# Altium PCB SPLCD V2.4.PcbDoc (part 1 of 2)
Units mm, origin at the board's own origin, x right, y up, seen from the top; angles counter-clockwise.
Board outline 130.07 x 120.05 mm, 4 copper layers (TopLayer, GND, PWR, BottomLayer); 151 components, 101 nets, 494 pads, 228 vias.
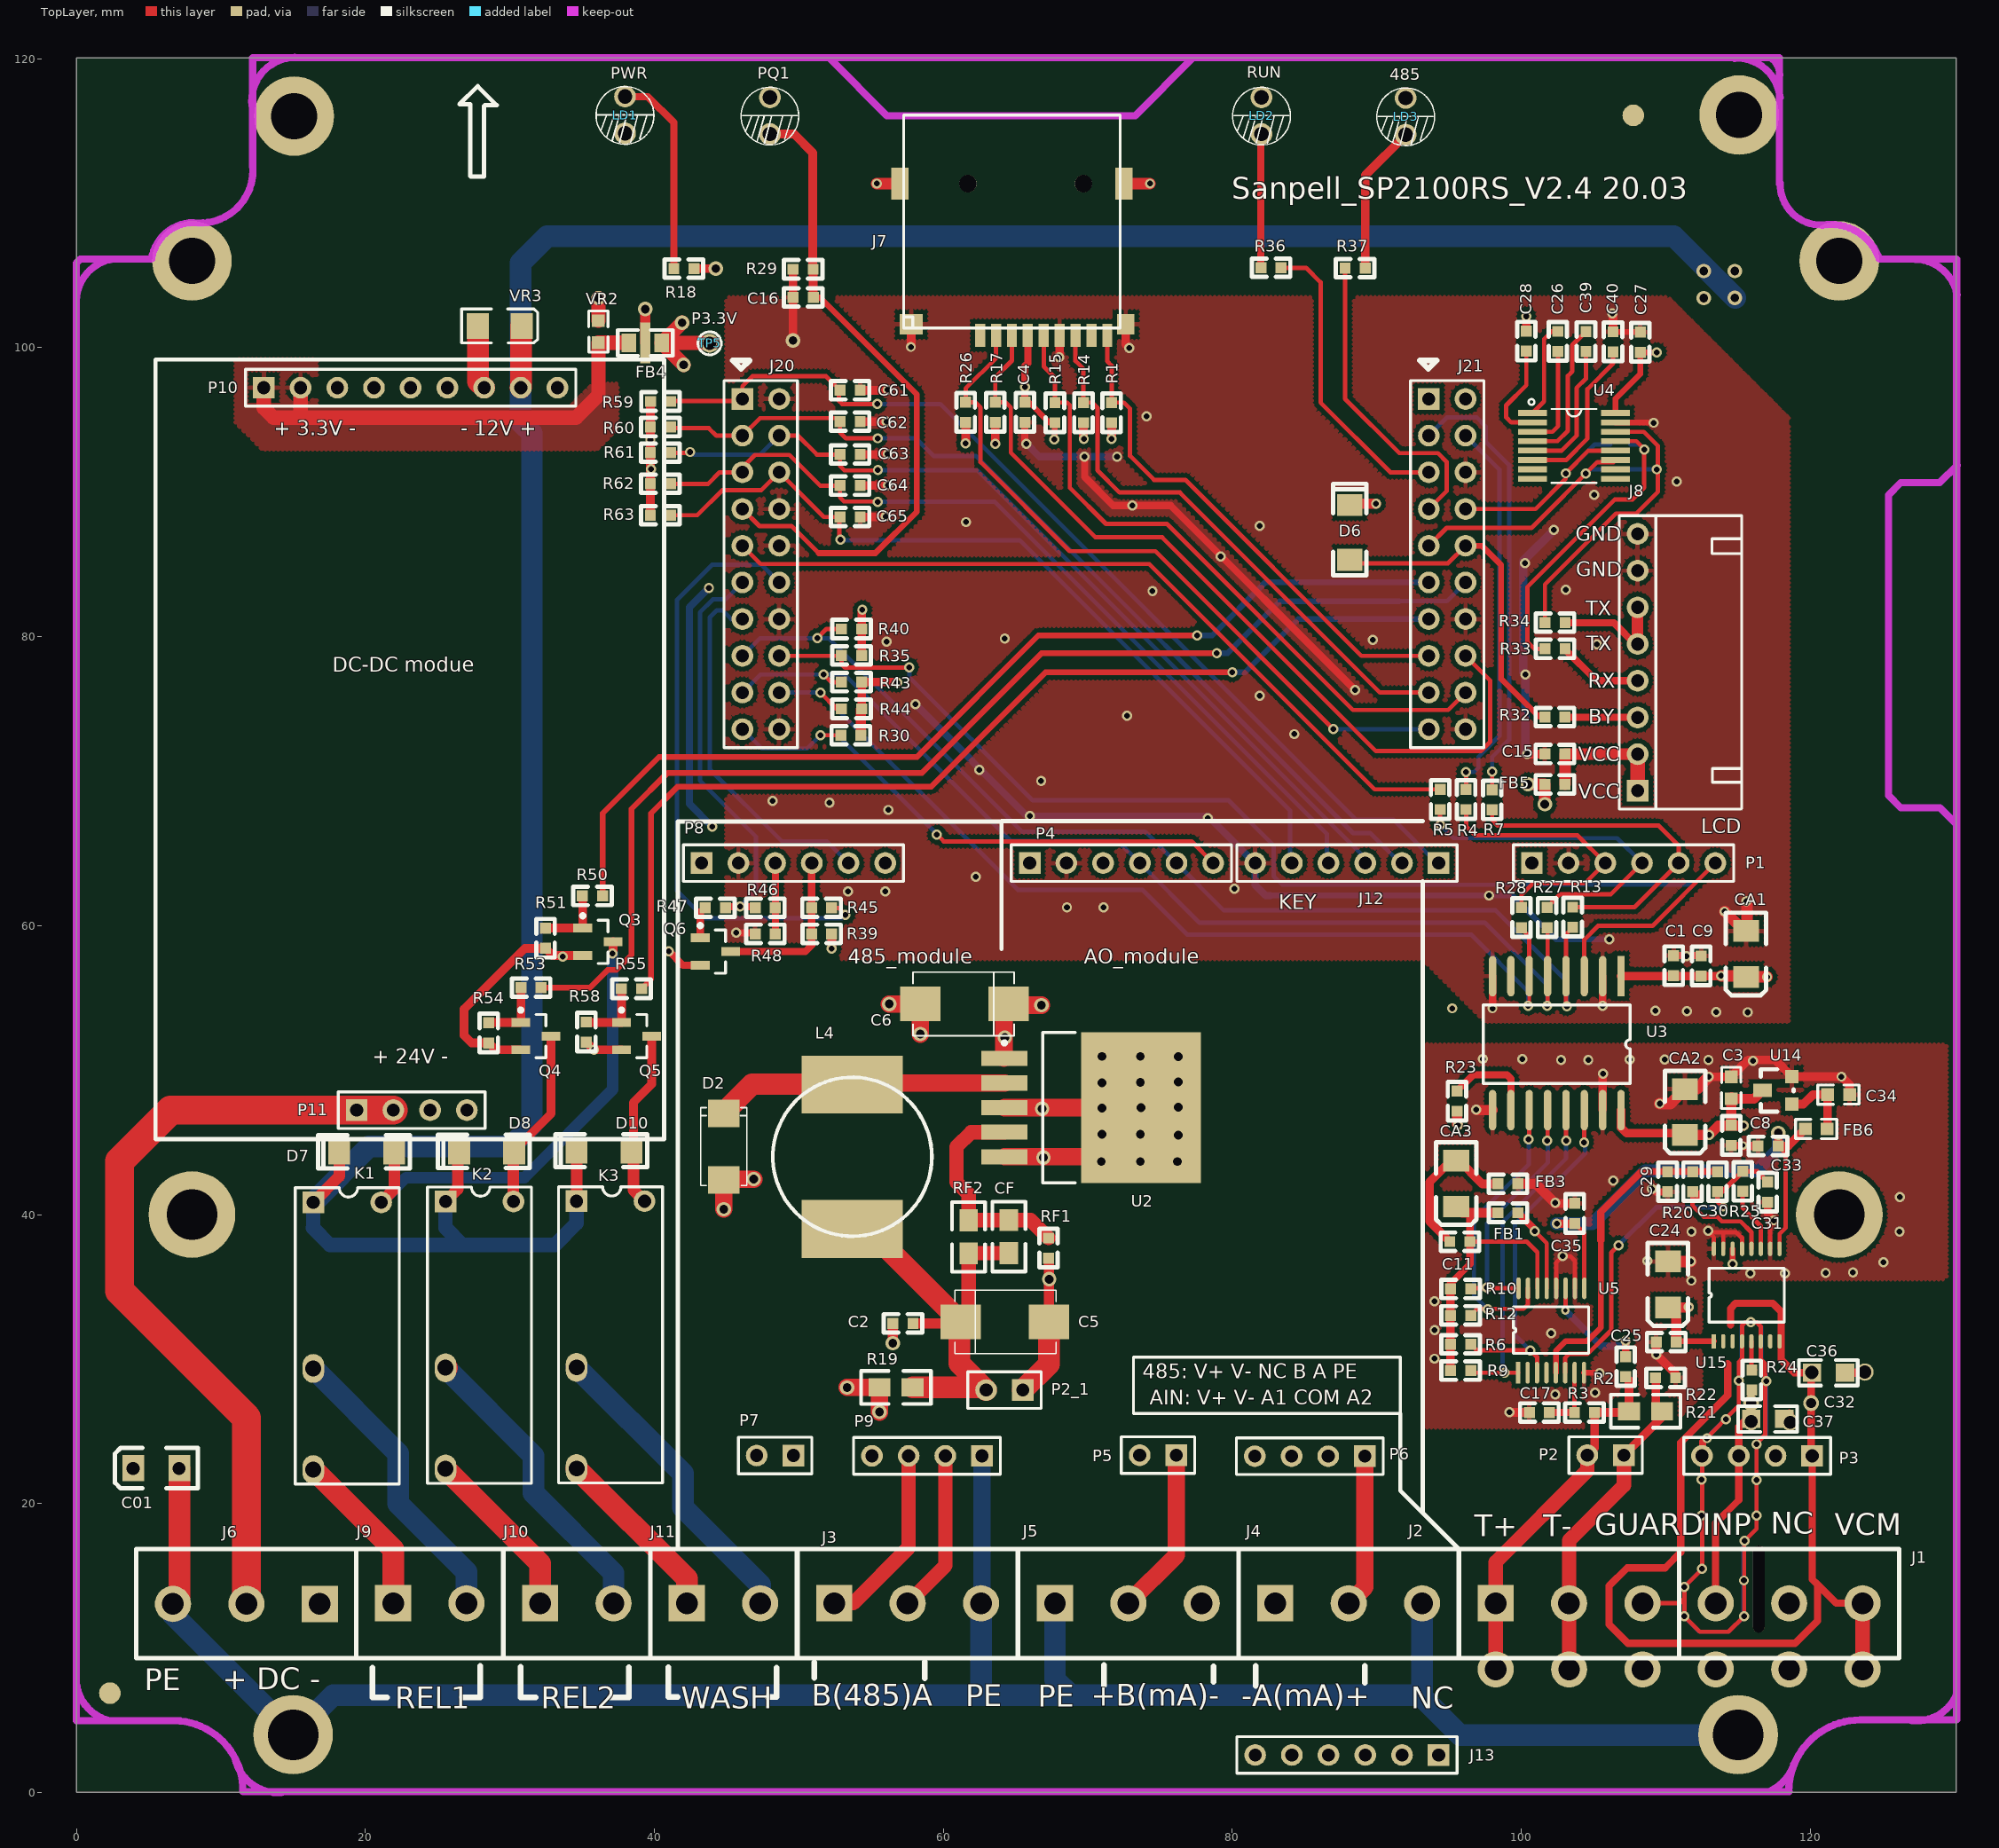
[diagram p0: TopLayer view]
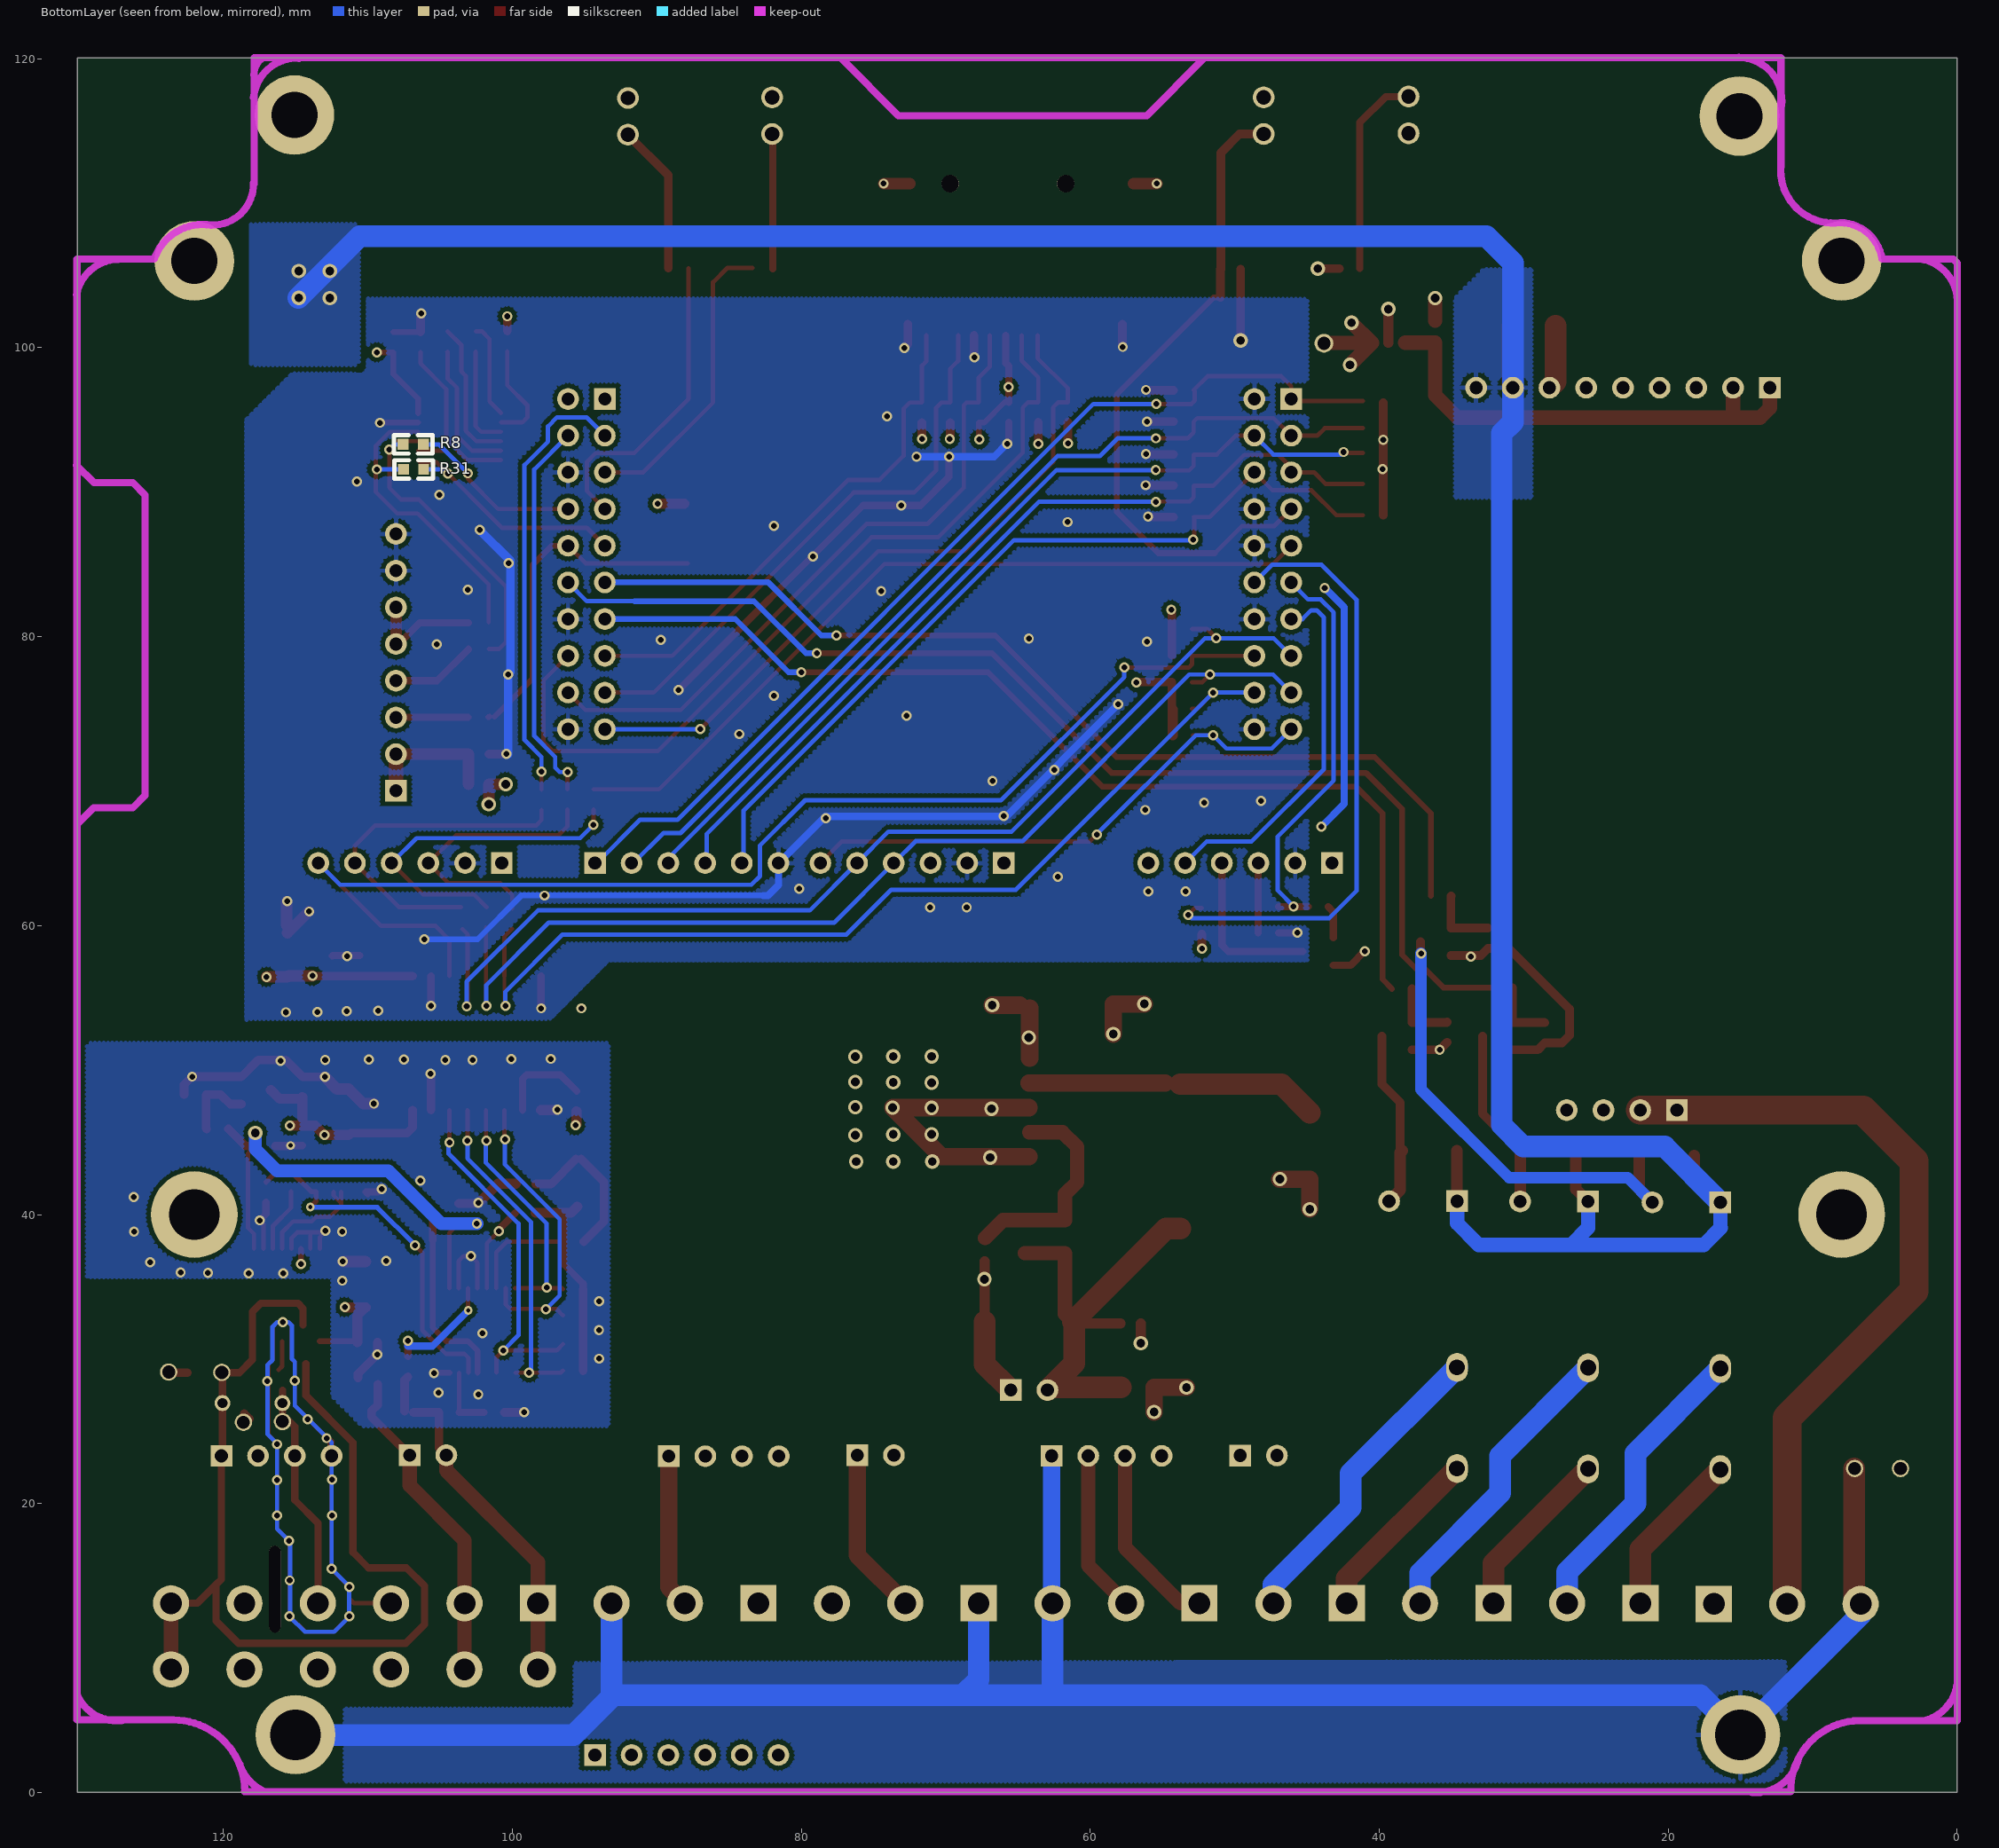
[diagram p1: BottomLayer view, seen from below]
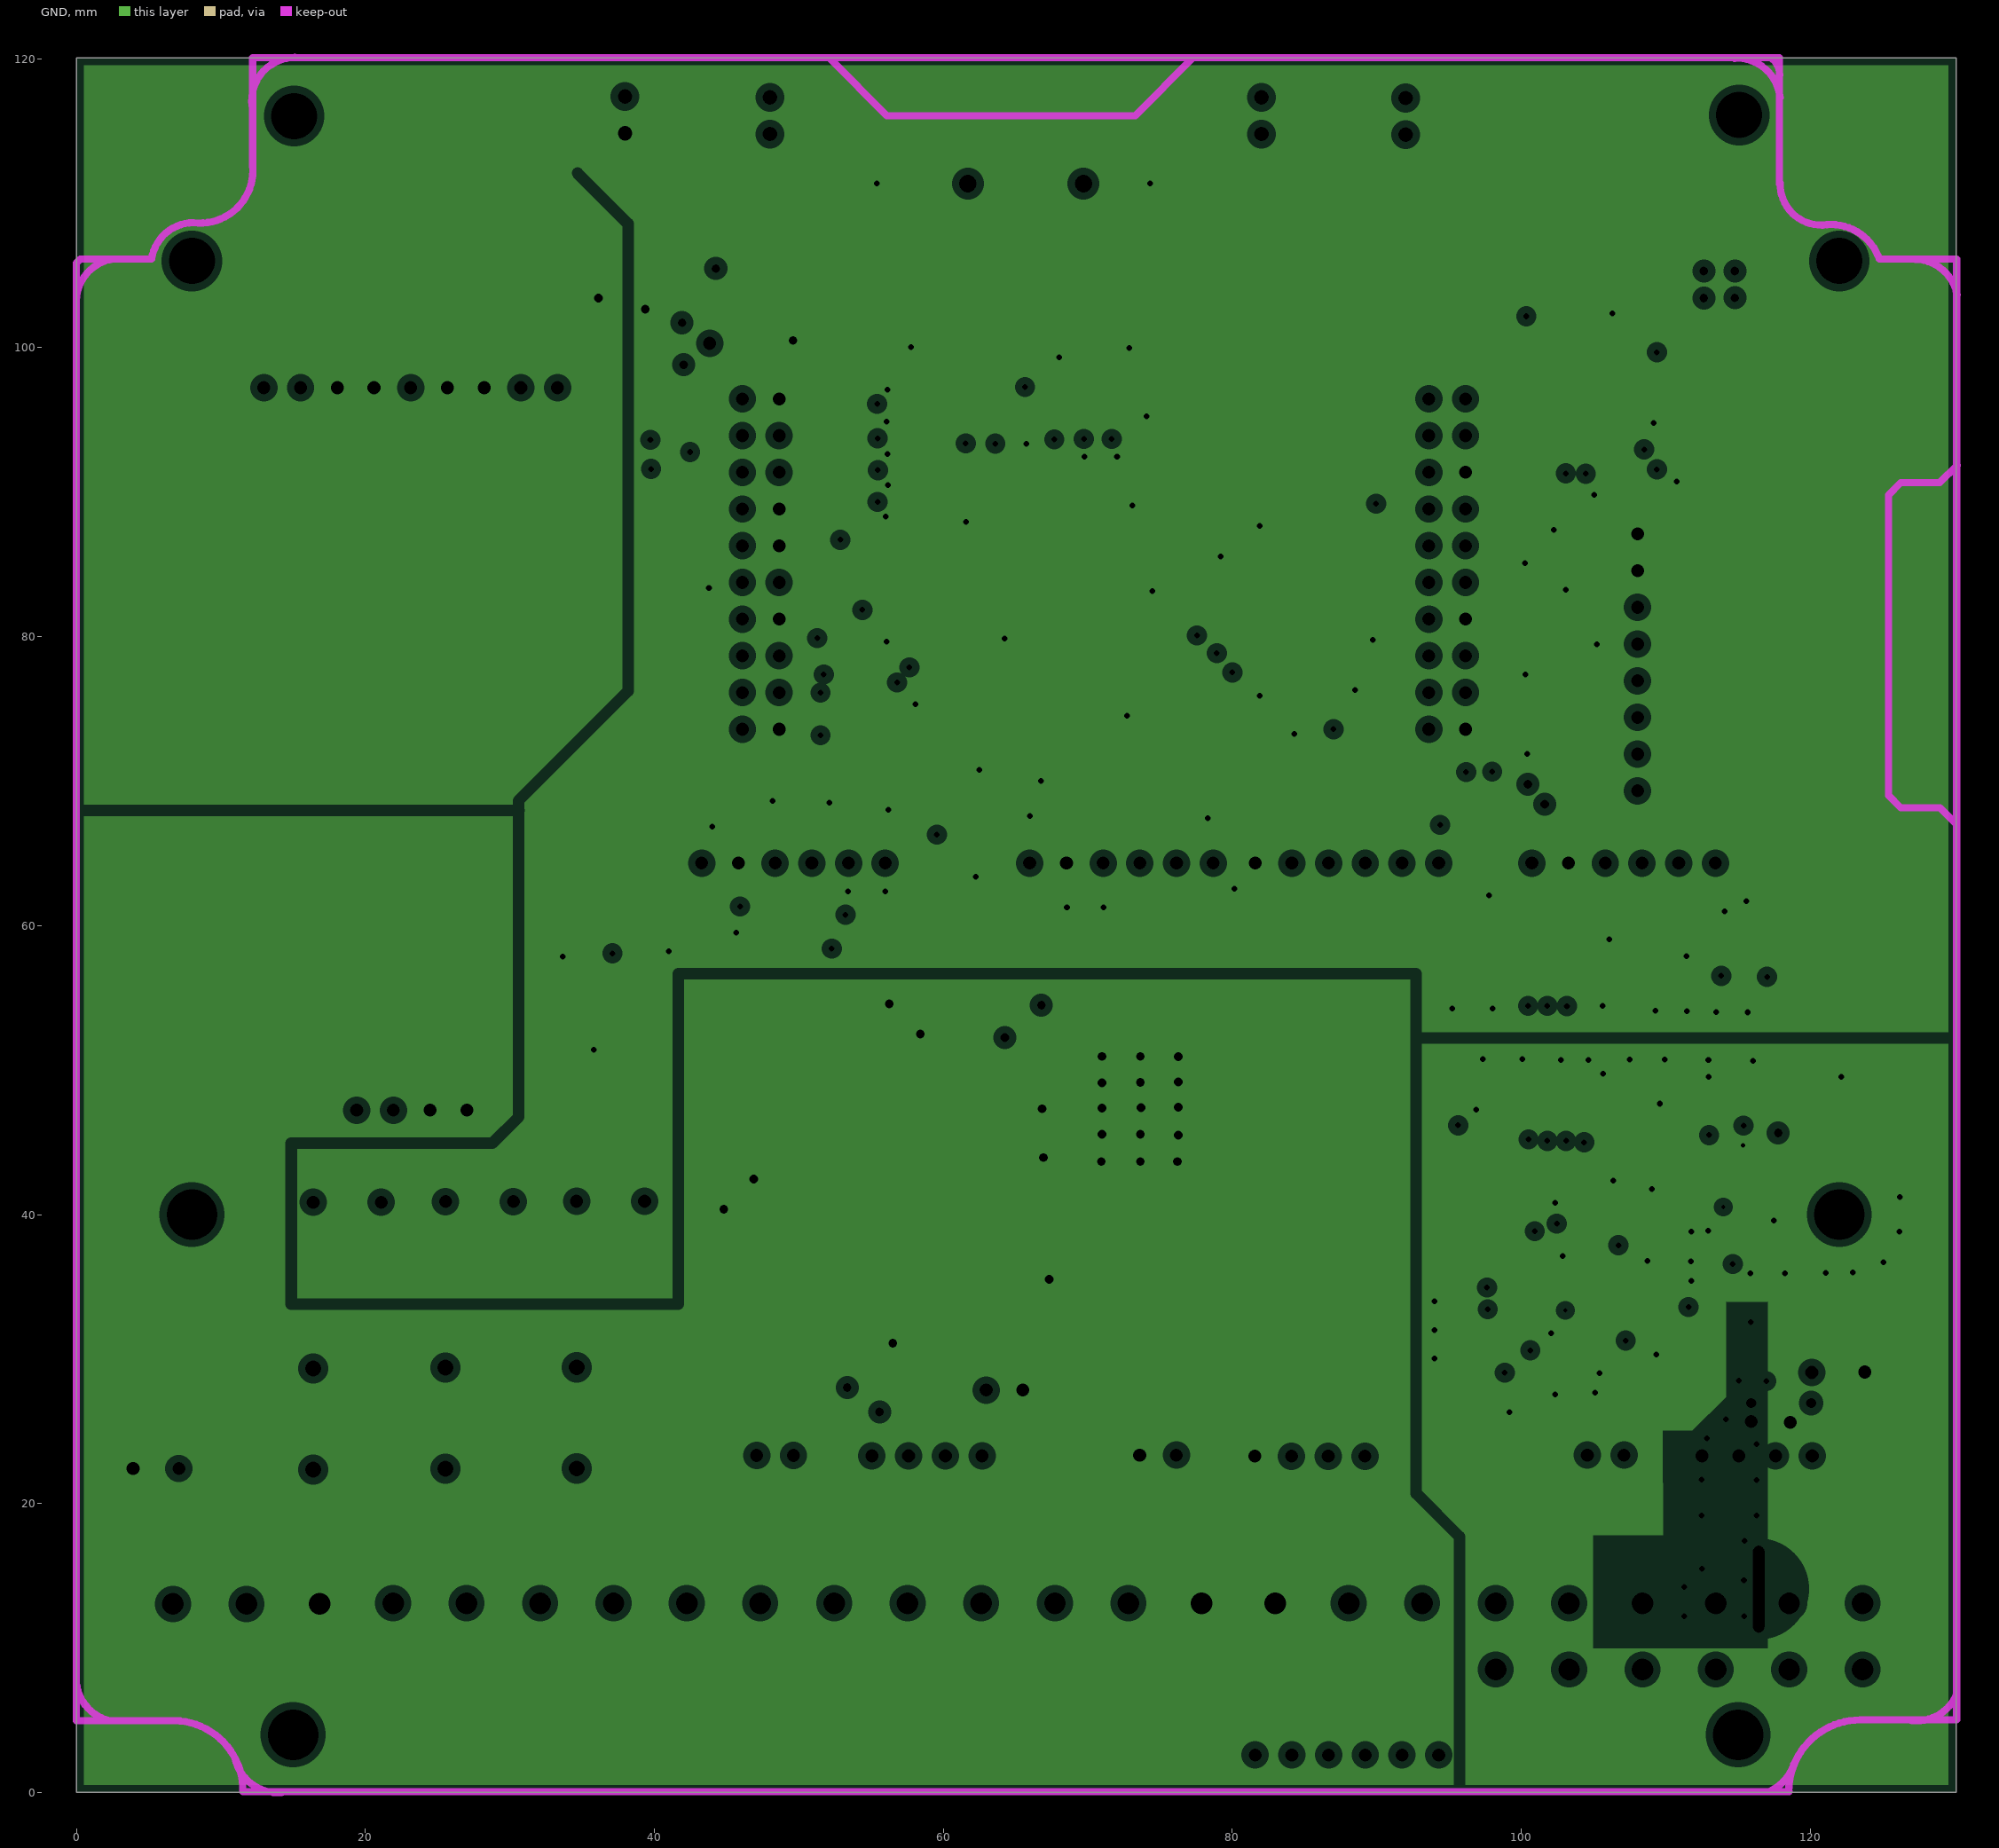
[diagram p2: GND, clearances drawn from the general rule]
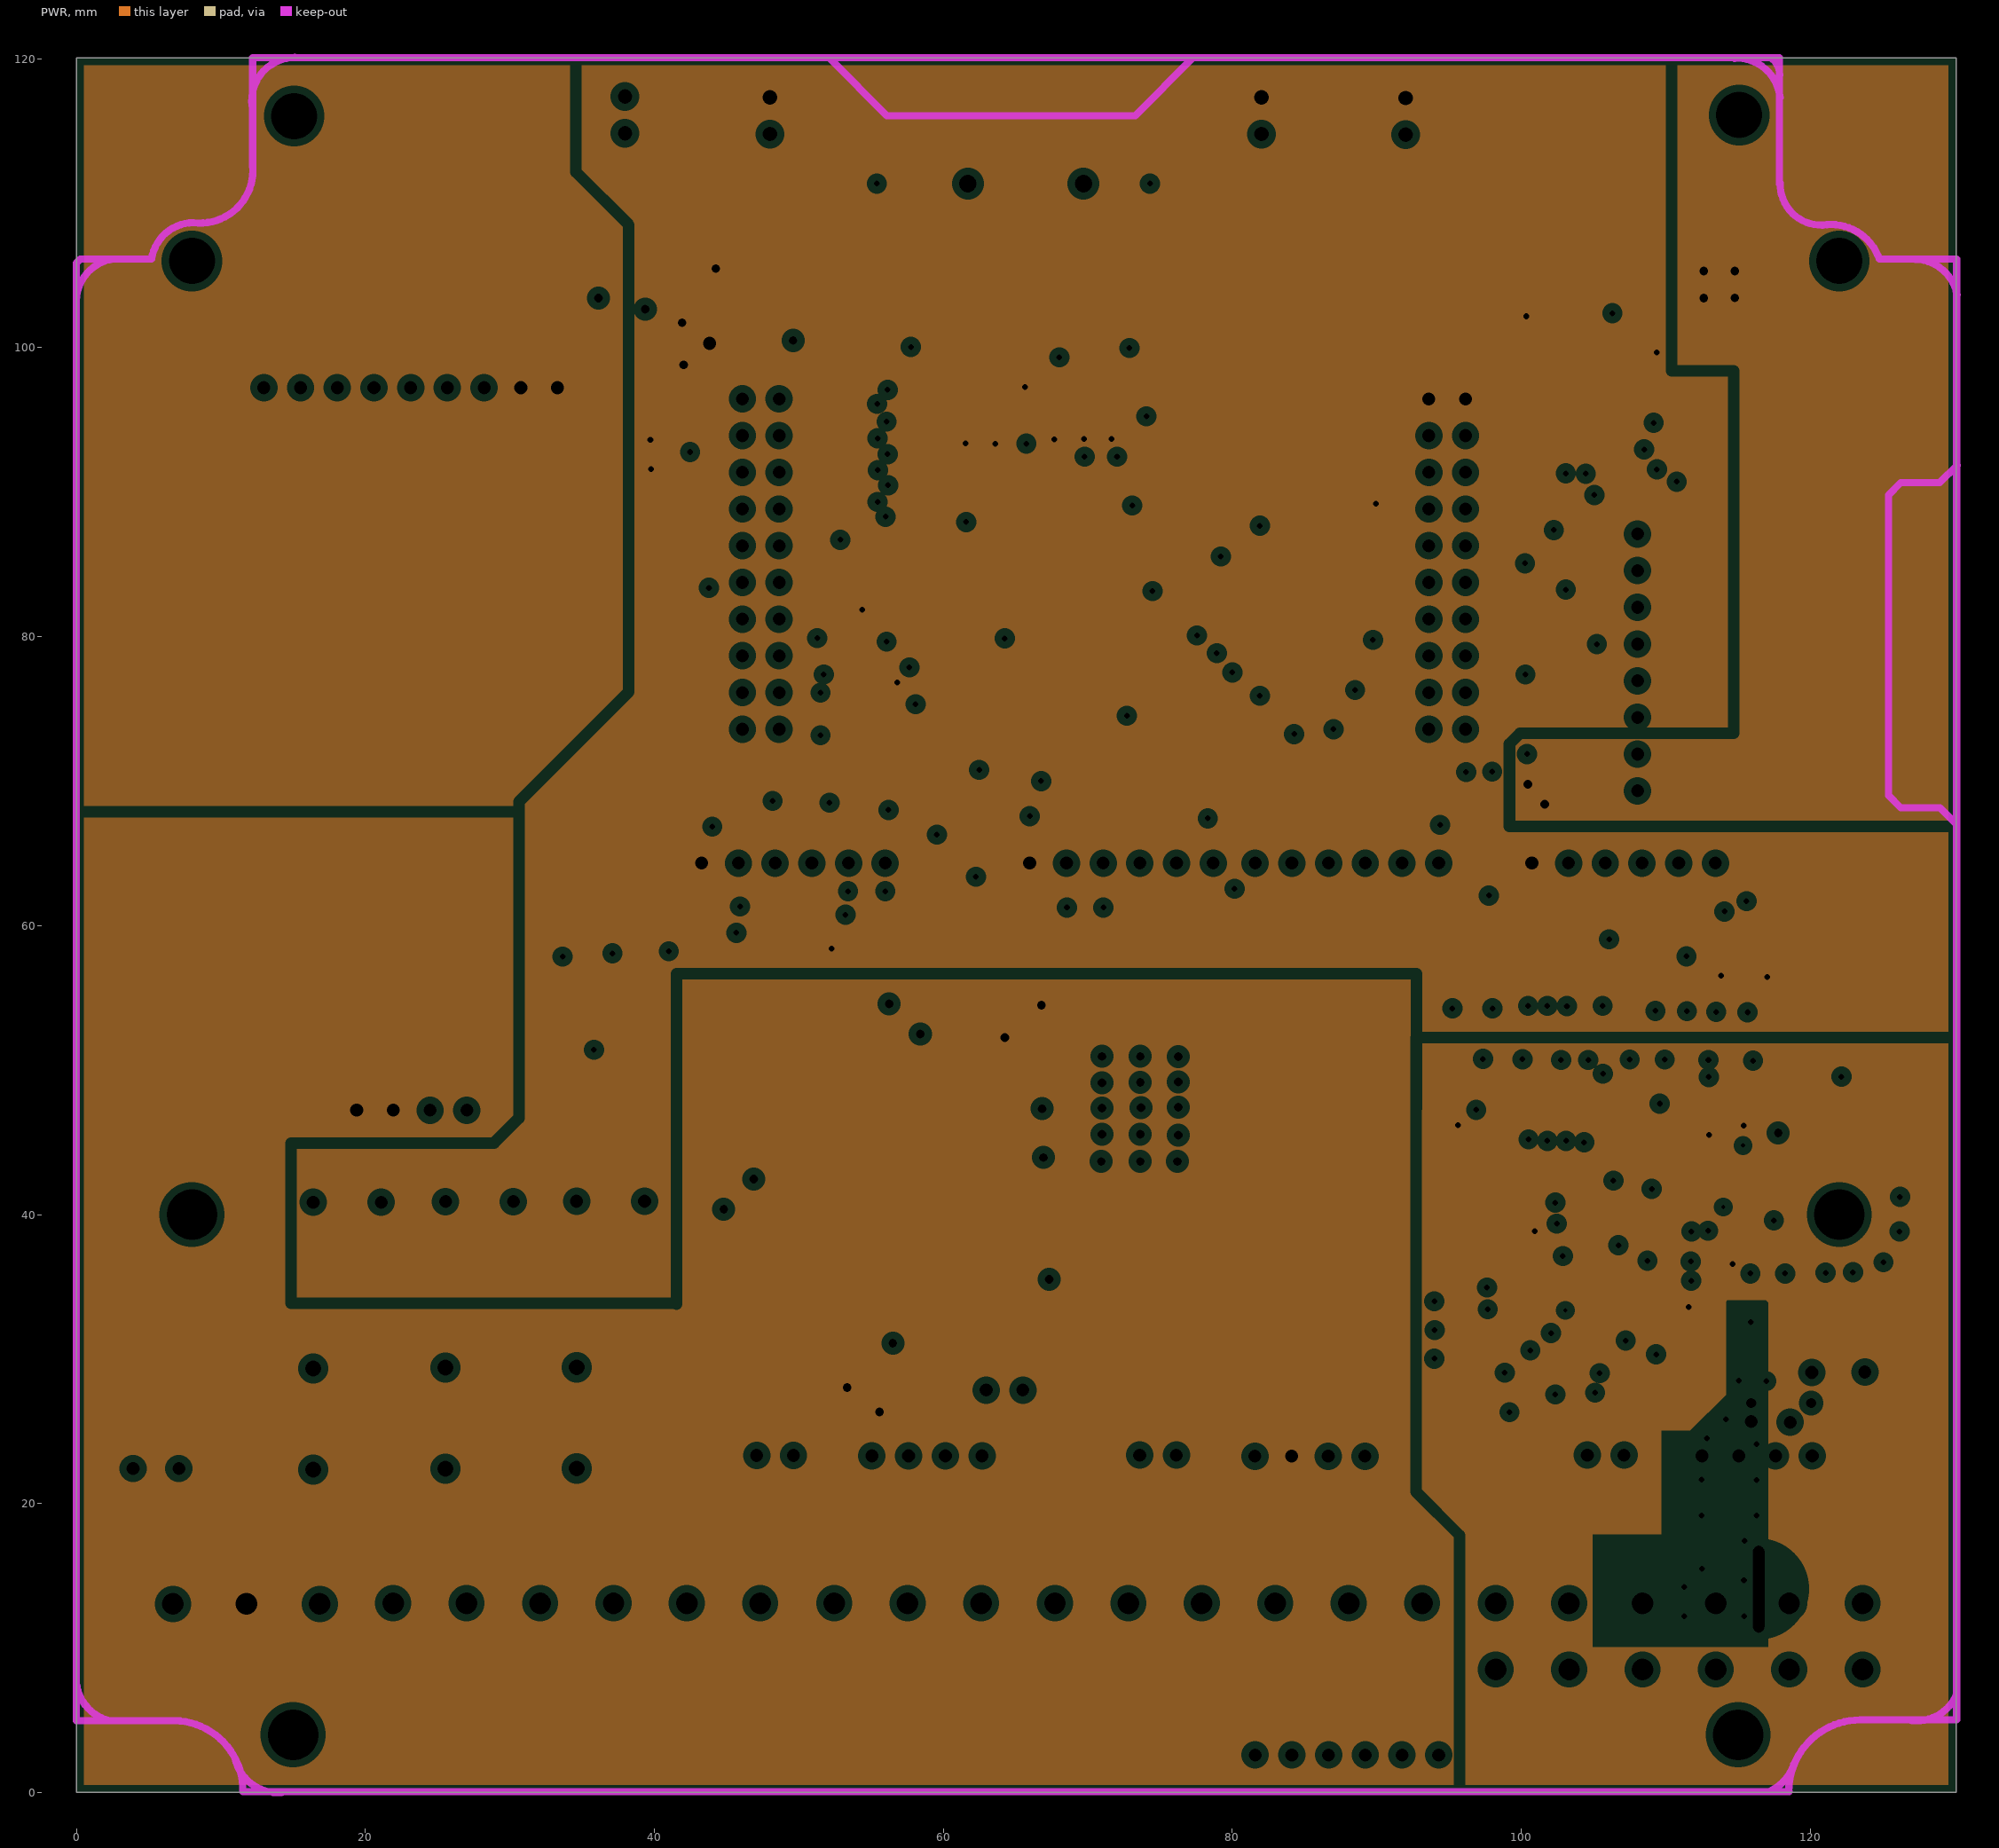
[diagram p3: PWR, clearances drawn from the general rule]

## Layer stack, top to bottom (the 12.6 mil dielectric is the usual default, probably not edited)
TopLayer: signal copper 0.0356
Dielectric: core 0.32, FR-4, Dk 4.8
GND: plane copper 0.0356
Dielectric: prepreg 0.32, FR-4, Dk 4.8
PWR: plane copper 0.0356
Dielectric: core 0.32, FR-4, Dk 4.8
BottomLayer: signal copper 0.0356

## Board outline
0,0 130.075,0 130.075,120.05 0,120.05

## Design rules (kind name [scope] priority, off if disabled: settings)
Clearance Clearance_poly [InPolygon] p1: gap=0.3
Clearance [All] p2: gap=0.15
ComponentClearance [All] p1: gap=0.15 collisioncheckmode=3 verticalgap=0.254 showdistances=FALSE
FabricationTestPointUsage TestPointUsage [All] p1: valid=0 allowmultiple=FALSE
FabricationTestpoint Testpoint [All] p1: side=3 testpointundercomponent=TRUE minsize=1.016 maxsize=2.54 preferedsize=1.524 minholesize=0.508 maxholesize=1.016 preferedholesize=0.813 testpointgrid=0.025 allowsidetop=TRUE allowsidebottom=TRUE usegrid=TRUE gridtolerance=0
HoleSize [All] p1: absolutevalues=TRUE maxlimit=8 minlimit=0.025 maxpercent=80.000 minpercent=20.000
MinimumSolderMaskSliver [All] p1: minsoldermaskwidth=0.15
PlaneClearance [All] p1: clearance=0.5
PlaneConnect [All] p1: planeconnectstyle=Relief reliefexpansion=0.5 reliefentries=4 reliefconductorwidth=0.3 reliefairgap=0.3
PolygonConnect PolygonConnect_via [IsVia] p1: connectstyle=Direct reliefconductorwidth=0.254 reliefentries=4 polygonreliefangle="90 Angle"
PolygonConnect [All] p2: connectstyle=Relief reliefconductorwidth=0.3 reliefentries=4 polygonreliefangle="90 Angle"
RoutingVias [All] p1: holewidth=0.305 width=0.61 viastyle="Through Hole" minholewidth=0.254 minwidth=0.508 maxholewidth=2 maxwidth=5
SilkToSilkClearance [All] p1: silktosilkclearance=0
SilkscreenOverComponentPads [IsPad] p1: minsilkscreentomaskgap=0
SolderMaskExpansion [All] p1: expansion=0.102
Width [All] p1: maxlimit=5.08 minlimit=0.1 preferedwidth=0.254
19 further rules are at their usual default settings.

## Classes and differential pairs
component class 02_INTERFACE: C1 C3 C4 C8 C9 C11 C15 C16 C17 C24 C25 C26 C27 C28 C29 C30 C31 C33 C34 C35 C36 C37 C39 C40 C61 C62 C63 C64 C65 CA1 CA2 CA3 D6 D7 D8 D10 FB1 FB3 FB5 FB6 J1 J2 J3 J4 J5 J7 J8 J9 J10 J11 J12 J13 J20 J21 K1 K2 K3 LD2 LD3 P1 P2 P3 P4 P5 P6 P7 P8 P9 PQ1 Q3 Q4 Q5 Q6 R1 R2 R3 R4 R5 R6 R7 R8 R9 R10 R12 R13 R14 R15 R17 R20 R21 R22 R23 R24 R25 R26 R27 R28 R29 R30 R31 R32 R33 R34 R35 R36 R37 R39 R40 R43 R44 R45 R46 R47 R48 R50 R51 R53 R54 R55 R58 R59 R60 R61 R62 R63 U3 U4 U5 U14 U15
component class 06_POWER: C01 C2 C5 C6 CF D2 FB4 J6 L4 LD1 P2_1 P10 P11 R18 R19 RF1 RF2 TP5 U2 VR2 VR3

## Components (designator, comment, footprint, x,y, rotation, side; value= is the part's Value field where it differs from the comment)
C01 "1nF/2kV" 1206 3.95,22.45 r180 top
C1 "10nF" 0603A 110.545,56.525 r90 top
C2 "0.1uF" 0603A 57.9,32.475 r180 top
C3 "4.7uF" SM0603 114.475,48.775 r90 top
C4 "0.1uF" 0603A 65.644,94.825 r90 top
C5 "100uF/50V" D 61.2,32.575 r0 top
C6 "100uF/50V" D 64.5,54.575 r180 top
C8 "0.1uF" 0603A 114.52,46.175 r270 top
C9 "0.1uF" 0603A 112.445,57.9 r270 top
C11 "0.1uF" 0603A 96.445,38.125 r180 top
C15 "0.1uF/50V" 0603A 103.019,71.875 r180 top
C16 "0.1uF" 0603 50.994,103.475 r180 top
C17 "1uF" 0603A 101.945,26.3 r180 top
C24 "10uF" 1206 110.145,33.577 r270 top
C25 "0.1uF" 0603A 110.725,31.175 r180 top
C26 "0.1uF" 0603A 102.519,101.125 r270 top
C27 "0.1uF" 0603A 108.225,101.07 r270 top
C28 "0.1uF" 0603A 100.344,99.75 r90 top
C29 "1uF" 0603A 110.119,41.575 r90 top
C30 "100pF" 0603A 113.569,42.975 r270 top
C31 "1uF" 0603A 117.044,42.25 r270 top
C33 "0.1uF" 0603A 117.775,44.75 r180 top
C34 "1uF" SM0603 121.95,48.35 r0 top
C35 "0.1uF" 0603A 103.695,39.375 r90 top
C36 "1nF" 0805A 120.1,29.05 r0 top
C37 "1nF" 0805A 115.9,25.85 r0 top
C39 "0.1uF" 0603A 104.469,99.725 r90 top
C40 "0.1uF" 0603A 106.344,99.7 r90 top
C61 "0.1uF" 0603A 52.844,97.05 r0 top
C62 "0.1uF" 0603A 52.844,94.875 r0 top
C63 "0.1uF" 0603A 52.844,92.6 r0 top
C64 "0.1uF" 0603A 52.844,90.45 r0 top
C65 "0.1uF" 0603A 52.844,88.275 r0 top
CA1 "10uF" 1206 115.55,56.447 r270 top
CA2 "10uF" 1206 111.32,45.502 r270 top
CA3 "10uF" 1206 95.495,40.552 r270 top
CF "10nF" 0805 64.525,39.625 r270 top
D2 "SS34" ZD 44.8,42.4 r90 top
D6 "1N4148" 1206D 88.125,85.5 r90 top
D7 "1N4148" 1206D 21.8,44.35 r180 top
D8 "1N4148" 1206D 30.1,44.375 r180 top
D10 "1N4148" 1206D 38.225,44.425 r180 top
FB1 "BLM18PG600SN1" 0603A 99.77,40.125 r180 top
FB3 "BLM18PG600SN1" 0603A 99.77,42.125 r180 top
FB4 "NFM21PC105B1C3" NFM21PC105 38.225,100.325 r0 top
FB5 "BLM18PG600SN1" 0603A 103.019,69.775 r180 top
FB6 "BLM18PG600SN1" SM0603 120.4,45.875 r180 top
J1 "P3-5.08" PH3-5.08mm#1 113.45,13.1 r0 top
J2 "P3-5.08" PH3-5.08mm#2 98.219,13.1 r0 top
J3 "P3-5.08" PH3-5.08mm#2 52.444,13.1 r0 top
J4 "P3-5.08" PH3-5.08mm#2 82.969,13.1 r0 top
J5 "P3-5.08" PH3-5.08mm#2 67.719,13.1 r0 top
J6 "P3-5.08" PH3-5.08mm#2 16.844,13.05 r180 top
J7 "Header 10" "TF Socket" 64.744,100.85 r180 top
J8 "XH-8AW" HDR1X8 108.041,69.325 r90 top
J9 "P2-5.08" PH2-5.08mm 21.919,13.1 r0 top
J10 "P2-5.08" PH2-5.08mm 32.094,13.1 r0 top
J11 "P2-5.08" PH2-5.08mm 42.244,13.1 r0 top
J12 "Header 6" HDR1X6 94.275,64.325 r180 top
J13 "Header 6" HDR1X6 94.275,2.6 r180 top (schematic designator J12)
J20 "Header 10X2" HDR2X10 46.094,96.45 r270 top
J21 "Header 10X2" HDR2X10 93.594,96.45 r270 top
K1 "ALDP124" ALDP124 15.144,21.35 r0 top
K2 "ALDP124" ALDP124 24.294,21.4 r0 top
K3 "ALDP124" ALDP124 33.37,21.425 r0 top
L4 "CDRH104R-470" "Inductor 10x10" 53.7,44 r270 top
LD1 "PWR" LED 37.969,117.375 r270 top
LD2 "RUN" LED 82.019,117.325 r270 top
LD3 "485" LED 91.995,117.275 r270 top
P1 "Header 6" HDR1X6 100.725,64.325 r0 top
P2 "Header 2" HDR1X2 107.1,23.35 r180 top
P2_1 "Header 2" HDR1X2 65.5,27.85 r180 top
P3 "Header 4" HDR1X4 120.125,23.3 r180 top
P4 "Header 6" HDR1X6 65.975,64.325 r0 top
P5 "Header 2" HDR1X2 76.125,23.35 r180 top
P6 "Header 4" HDR1X4 89.175,23.275 r180 top
P7 "Header 2" HDR1X2 49.625,23.325 r180 top
P8 "Header 6" HDR1X6 43.275,64.325 r0 top
P9 "Header 4" HDR1X4 62.675,23.3 r180 top
P10 "Header 9" HDR1X9 12.975,97.225 r0 top
P11 "Header 4" HDR1X4 19.4,47.225 r0 top
PQ1 "MI3-P" LED 47.994,117.325 r270 top
Q3 "MMBT3904" SOT23_N 36.094,58.875 r0 top
Q4 "MMBT3904" SOT23_N 31.8,52.35 r0 top
Q5 "MMBT3904" SOT23_N 38.769,52.35 r0 top
Q6 "MMBT3904" SOT23_N 44.225,58.2 r0 top
R1 "10K" 0603A 71.644,96.2 r270 top
R2 "0R" 0603A 107.22,28.775 r90 top
R3 "10K" 0603A 105.07,26.3 r180 top
R4 "0R" 0603A 96.175,69.425 r270 top
R5 "0R" 0603A 94.375,69.425 r270 top
R6 "100K" 0603A 95.095,31.025 r0 top
R7 "0R" 0603A 97.975,69.4 r270 top
R8 "NC" 0603A 107.547,93.3 r180 bottom
R9 "100K" 0603A 95.095,29.2 r0 top
R10 "100K" 0603A 95.095,34.85 r0 top
R12 "100K" 0603A 95.095,33.025 r0 top
R13 "0R" 0603A 103.55,61.275 r270 top
R14 "10K" 0603A 69.694,96.2 r270 top
R15 "10K" 0603A 67.719,96.2 r270 top
R17 "10K" 0603A 63.594,96.225 r270 top
R18 "1K" 0603A 41.35,105.475 r0 top
R19 "NC" 0805 55.575,28.025 r0 top (schematic designator RF2)
R20 "10K" 0603A 111.844,41.575 r90 top
R21 "5K 0.1%" 0805 109.75,26.4 r180 top
R22 "0R" 0603A 109.275,28.7 r0 top
R23 "4.7K" 0603A 95.545,48.55 r270 top
R24 "10M" 0603A 115.95,27.85 r90 top
R25 "10K" 0603A 115.319,41.6 r90 top
R26 "10K" 0603A 61.544,96.225 r270 top
R27 "0R" 0603A 101.775,61.25 r270 top
R28 "0R" 0603A 100,61.25 r270 top
R29 "100K" 0603A 49.594,105.425 r0 top
R30 "47K" 0603A 54.297,73.175 r180 top (schematic designator R44)
R31 "NC" 0603A 107.525,91.575 r180 bottom
R32 "NC" 0603A 103.019,74.425 r180 top
R33 "100R" 0603A 103.025,79.15 r180 top
R34 "100R" 0603A 103.025,80.975 r180 top
R35 "47K" 0603A 54.344,78.7 r180 top
R36 "1K" 0603A 83.375,105.525 r180 top
R37 "1K" 0603A 87.8,105.5 r0 top
R39 "4.7K" 0603A 52.275,59.425 r180 top
R40 "47K" 0603A 54.344,80.525 r180 top
R43 "47K" 0603A 54.344,76.85 r180 top
R44 "47K" 0603A 54.344,75 r180 top
R45 "NC" 0603A 50.875,61.225 r0 top
R46 "NC" 0603A 48.375,61.225 r180 top
R47 "1K" 0603A 43.525,61.225 r0 top
R48 "0R" 0603A 48.375,59.425 r180 top
R50 "1K" 0603A 35.02,62.05 r0 top
R51 "100K" 0603A 32.469,59.825 r270 top
R53 "1K" 0603A 30.769,55.7 r0 top
R54 "100K" 0603A 28.544,53.275 r270 top
R55 "1K" 0603A 37.719,55.625 r0 top
R58 "100K" 0603A 35.294,53.325 r270 top
R59 "47K" 0603A 41.125,96.275 r180 top
R60 "47K" 0603A 41.119,94.5 r180 top
R61 "47K" 0603A 41.119,92.725 r180 top
R62 "47K" 0603A 41.119,90.575 r180 top
R63 "47K" 0603A 41.119,88.4 r180 top
RF1 "1K" 0603A 67.275,36.975 r90 top
RF2 "3K 1%" 0805 61.75,37.3 r90 top
TP5 "P3.3V" "TEST POINT" 43.825,100.3 r180 top
U2 "LM2596S-ADJ" TS5B_N 70.225,47.4 r0 top
U3 "ADuM5401ARWZ" ADUM1401 106.895,56.5 r270 top
U4 "SP3232EEY-L" TSSOP-16 100.769,95.475 r0 top
U5 "AD7793BRU" AD7793 102.07,31.975 r90 top
U14 "AD1584BRTZ" SOT-23 116.575,49.975 r90 top
U15 "LMP91200" LMP91200 115.594,34.425 r0 top
VR2 "V3.5MLA0603N" SM0603 36.175,101.1 r270 top (schematic designator VA1)
VR3 "V14MLA1206N" SM1206 29.3,101.5 r0 top

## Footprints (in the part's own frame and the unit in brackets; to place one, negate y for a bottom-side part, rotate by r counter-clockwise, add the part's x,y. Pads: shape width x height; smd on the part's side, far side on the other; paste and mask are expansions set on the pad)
0603 [mil]
  rect 30x30 smd: 1(0,0) 2(55,0)
  silkscreen extent -25,-25 80,25
0603A [mil]
  rect 30x30 smd: 1(0,0) 2(55,0)
  silkscreen extent -25,-25 80,25
0805 [mil]
  rect 60x50 smd: 1(0.39,0.31) 2(90.39,0.31)
  silkscreen extent -50,-45 140,45
0805A [mm]
  rect 1.27x1.27 smd: 1(0.01,0.008) 2(2.296,0.008)
  silkscreen extent -0.89,-0.89 3.17,0.89
1206 [mm]
  rect 1.5x1.8 smd: 1(0,0) 2(-3.175,0)
  silkscreen extent -4.45,-1.4 1.27,1.4
1206D [mil]
  rect 60x70 smd: 1(-7.5,0.1) 2(142.11,0.1)
  silkscreen extent -50,-45 200,45
AD7793 [mm]
  rect 1.5x0.3 smd: 1(-2.921,2.286)
  oval 1.5x0.3 smd: 2(-2.921,1.636) 3(-2.921,0.986) 4(-2.921,0.336) 5(-2.921,-0.314) 6(-2.921,-0.964) 7(-2.921,-1.614) 8(-2.921,-2.264) 9(2.921,-2.286) 10(2.921,-1.636) 11(2.921,-0.986) 12(2.921,-0.336) 13(2.921,0.314) 14(2.921,0.964) 15(2.921,1.614) 16(2.921,2.264)
  silkscreen extent -1.59,-2.59 1.64,2.61
ADUM1401 [mm]
  rect 2.8x0.51 smd: 1(0,0)
  oval 2.8x0.51 smd: 2(0,-1.27) 3(0,-2.54) 4(0,-3.81) 5(0,-5.08) 6(0,-6.35) 7(0,-7.62) 8(0,-8.89) 9(9.271,-8.89) 10(9.271,-7.62) 11(9.271,-6.35) 12(9.271,-5.08) 13(9.271,-3.81) 14(9.271,-2.54) 15(9.271,-1.27) 16(9.271,0)
  silkscreen extent 1.99,-9.53 7.43,0.64
ALDP124 [mm]
  oval 1.5x2 hole 1.1: 1(1.25,8) 7(1.25,1)
  round 1.5 hole 0.9: 3(5.95,19.5)
  rect 1.5x1.5 hole 0.9: 5(1.25,19.5)
  silkscreen extent 0,0 7.2,20.5
D [mil]
  rect 110x94.49 smd: 1(0,0) 2(240,0)
  silkscreen extent -16,-87 260,87
HDR1X2 [mm] "Connector; Header; 2 Position"
  rect 1.5x1.5 hole 0.9: 1(0,0)
  round 1.5 hole 0.9: 2(2.54,0)
  silkscreen extent -1.27,-1.27 3.81,1.27
HDR1X4 [mm] "Connector; Header; 4 Position"
  rect 1.5x1.5 hole 0.9: 1(0,0)
  round 1.5 hole 0.9: 2(2.54,0) 3(5.08,0) 4(7.62,0)
  silkscreen extent -1.27,-1.27 8.89,1.27
HDR1X6 [mm] "Connector; Header; 6 Position"
  rect 1.5x1.5 hole 0.9: 1(0,0)
  round 1.5 hole 0.9: 2(2.54,0) 3(5.08,0) 4(7.62,0) 5(10.16,0) 6(12.7,0)
  silkscreen extent -1.27,-1.27 13.97,1.27
HDR1X8 [mm] "Connector; Header; 8 Position"
  rect 1.5x1.5 hole 0.9: 1(0,0)
  round 1.5 hole 0.9: 2(2.54,0) 3(5.08,0) 4(7.62,0) 5(10.16,0) 6(12.7,0) 7(15.24,0) 8(17.78,0)
  silkscreen extent -1.27,-1.27 19.05,1.27
HDR1X9 [mm] "Connector; Header; 9 Position"
  rect 1.5x1.5 hole 0.9: 1(0,0)
  round 1.5 hole 0.9: 2(2.54,0) 3(5.08,0) 4(7.62,0) 5(10.16,0) 6(12.7,0) 7(15.24,0) 8(17.78,0) 9(20.32,0)
  silkscreen extent -1.27,-1.27 21.59,1.27
HDR2X10 [mm] "Connector; Header; 10x2 Position"
  rect 1.5x1.5 hole 0.9: 1(0,0)
  round 1.5 hole 0.9: 2(0,2.54) 3(2.54,0) 4(2.54,2.54) 5(5.08,0) 6(5.08,2.54) 7(7.62,0) 8(7.62,2.54) 9(10.16,0) 10(10.16,2.54) 11(12.7,0) 12(12.7,2.54) 13(15.24,0) 14(15.24,2.54) 15(17.78,0) 16(17.78,2.54) 17(20.32,0) 18(20.32,2.54) 19(22.86,0) 20(22.86,2.54)
  silkscreen extent -1.27,-1.27 24.13,3.81
"Inductor 10x10" [mm] "Magnetic-Core Inductor with Winding Polarity Marking; 2 Leads"
  rect 4x7 smd: 1(-5,0) 2(5,0)
  silkscreen extent -5.5,-5.5 5.5,5.5
LED [mm]
  round 1.5 hole 1: 1(0,0) 2(2.54,0)
  silkscreen extent -0.7,-2 3.3,2
LMP91200 [mm]
  rect 0.3x1 smd: 1(-2.275,-3.2)
  oval 0.3x1 smd: 2(-1.625,-3.2) 3(-0.975,-3.2) 4(-0.325,-3.2) 5(0.325,-3.2) 6(0.975,-3.2) 7(1.625,-3.2) 8(2.275,-3.2) 9(2.275,3.2) 10(1.625,3.2) 11(0.975,3.2) 12(0.325,3.2) 13(-0.325,3.2) 14(-0.975,3.2) 15(-1.625,3.2) 16(-2.275,3.2)
  silkscreen extent -2.6,-1.87 2.6,1.87
NFM21PC105 [mm]
  rect 1x1.27 smd: 1(0.01,0.008) 2(2.286,0)
  rect 0.7x2.8 smd: 3(1.143,0)
  silkscreen extent -0.76,-0.89 3.05,0.89
PH2-5.08mm [mm]
  rect 2.5x2.5 hole 1.5: 1(0,0)
  round 2.5 hole 1.5: 2(5.08,0)
  silkscreen extent -2.54,-3.81 7.62,3.75
PH3-5.08mm#1 [mm]
  round 2.5 hole 1.5: 1(0,0) 2(5.08,0) 3(10.16,0)
  silkscreen extent -2.54,-3.81 12.7,3.75
PH3-5.08mm#2 [mm]
  rect 2.5x2.5 hole 1.5: 1(0,0)
  round 2.5 hole 1.5: 2(5.08,0) 3(10.16,0)
  silkscreen extent -2.54,-3.81 12.7,3.75
SM0603 [mil]
  rect 35x35 smd: 1(-30,-2) 2(30,-2)
  silkscreen extent -57,-28 56,24
SM1206 [mil]
  rect 60x70 smd: 1(-59.5,0) 2(59.5,0)
  silkscreen extent -104,-46 104,46
SOT23_N [mm] "SOT23, 3-Leads, Body 2.9x1.3mm, Pitch 0.95mm, Lead Span 2.3mm, IPC Medium Density"
  rect 1.3x0.6 smd: 1(-1.05,0.95) 2(-1.05,-0.95) 3(1.05,0)
  silkscreen extent -1.17,-1.5 0.7,1.92, body extent -0.7,-1.5 0.7,1.5, height 1.1
SOT-23 [mil]
  rect 36x36 smd: 1(-91.86,-84.66) 2(-16.86,-84.66)
  rect 36x50 smd: 3(-53.86,-4.66)
  silkscreen extent -112,-90 3,0
"TEST POINT" [mm]
  round 1.3 hole 0.9: 1(0,0)
  silkscreen extent -0.8,-0.8 0.8,0.8
"TF Socket" [mm]
  rect 0.7x1.6 smd: 1(2.2,0) 2(1.1,0) 3(0,0) 4(-1.1,0) 5(-2.2,0) 6(-3.3,0) 7(-4.4,0) 8(-5.5,0) 9(-6.6,0)
  rect 1.2x1.4 smd: 10(-7.877,-0.762)
  rect 1.2x2.2 smd: 10(-7.75,-10.5) 10(7.75,-10.5)
  rect 1.6x1.4 smd: 10(6.977,-0.762)
  round 1.2 hole 1.2: ""(-4.95,-10.5) ""(3.05,-10.5)
  silkscreen extent -7.49,-15.24 7.49,-0.51
TS5B_N [mm] "D2-PAK, 6-Leads, Body 8.6x10.2mm, Pitch 1.7mm, Lead Span 14.1mm, IPC Medium Density"
  rect 3.2x1.05 smd: 1(-6,3.4) 2(-6,1.7) 3(-6,0) 4(-6,-1.7) 5(-6,-3.4)
  rect 8.3x10.45 smd: 6(3.45,0)
  silkscreen extent -6.12,-5.2 -1.1,5.2, body extent -3.35,-5.2 6.05,5.2, height 4.65
TSSOP-16 [mil]
  rect 78x16 smd: 1(0,0) 2(0,-25.59) 3(0,-51.18) 4(0,-76.77) 5(0,-102.36) 6(0,-127.95) 7(0,-153.54) 8(0,-179.13) 9(226,-179.13) 10(226,-153.54) 11(226,-127.95) 12(226,-102.36) 13(226,-76.77) 14(226,-51.18) 15(226,-25.59) 16(226,0)
  silkscreen extent -11,-190 174,38
ZD [mm]
  rect 1.9x2.2 smd: 1(0,0) 2(4.6,0)
  silkscreen extent -0.4,-1.6 5,1.6

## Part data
C01 C1 C2 C3 C4 C16 C17 C25 C29 C30 C31 C33 C34 C35 C36 C37 CF: library part CAP, "Capacitor"
C5 C6 C24 CA1 CA2 CA3: library part CAPE, "Capacitor"
C8 C9 C11: library part CA, "电?"
C15 C61 C62 C63 C64 C65: library part Cap, "Capacitor, X7R Ceramic"
C26 C28 C39 C40: library part Cap, "'Capacitor, X7R Ceramic"
C27: library part CAP, "'Capacitor, X7R Ceramic"
D2: library part "D Schottky", "Schottky Diode"
D6 D7 D8 D10: library part "Diode 1N4148", "High Conductance Fast Diode"
FB1 FB3: library part INDUCTOR
FB4 FB5 FB6: library part Inductor, "Inductor"
J1 J2 J3 J4 J5 J6: library part "Header 3", "Header, 3-Pin"
J7: "Header, 10-Pin"
J8: library part "Header 8", "Header, 8-Pin"
J9 J10 J11: library part "Header 2", "Header, 2-Pin"
J12 J13 P1 P4 P8: "Header, 6-Pin"
J20 J21: "Header, 10-Pin, Dual row"
K1 K2 K3: library part S1A120000, "24V coil, 5A SPST Relay"
L4: library part Inductor, "Inductor, 47uH, 2A"
LD1 LD2 LD3: library part LED0, "Typical INFRARED GaAs LED"
P2 P2_1 P5 P7: "Header, 2-Pin"
P3 P6 P9 P11: "Header, 4-Pin"
P10: "Header, 9-Pin"
PQ1: library part "Photo NPN", "NPN Phototransistor"
Q3 Q4 Q5 Q6: "NPN Switching Transistor"
R1 R4 R5 R7 R13 R14 R15 R17 R18 R26 R27 R28 R29 R30 R32 R33 R34 R35 R36 R37 R39 R40 R43 R44 R45 R46 R47 R48 R50 R51 R53 R54 R55 R58 R59 R60 R61 R62 R63: library part R, "电?"
R2 R3 R6 R8 R9 R10 R12 R19 R20 R21 R22 R23 R24 R25 R31 RF1 RF2: library part RE, "电?"
TP5: library part PAD
U2: "SIMPLE SWITCHER?Power Converter 150 KHz 3A Step-Down Voltage Regulator, 5-pin TO-263"
U3: library part ADUM1401, "1Mbps Data Rate, 100ns Propagation delay"
U5: library part AD7793
U14: library part "Header 3", "4.096V reference"
VR2 VR3: library part "D Zener", "Zener Diode"

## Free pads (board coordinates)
  round 1.5 smd: 0(2.325,6.875) 0(107.75,116.075)
  round 6 hole 3.5: 1(8,40) 1(122,40)
  round 5.5 hole 3.2: 1(8,106) 1(122,106) ""(15.069,116.025) ""(115.069,116.1)
  round 5.5 hole 3.5: 1(15,4) 2(115,4)
  round 2.5 hole 1.5: 1(98.225,8.525) 2(103.305,8.525) 3(108.385,8.525) 4(113.45,8.525) 5(118.53,8.525) 6(123.61,8.525)
  round 1.2 hole 0.9: ""(3.925,22.425) ""(7.1,22.425) ""(115.9,25.675) ""(118.6,25.625) ""(120.1,29.075) ""(123.775,29.1)
  round 1.1 hole 0.7: ""(115.9,26.95) ""(120.05,26.95)
  oval 0.8x6 hole 0.8 slot 6 at 90 deg: ""(116.425,14.075)

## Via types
v1: diameter 0.7, hole 0.4, TopLayer to BottomLayer, 185 vias
v2: diameter 1, hole 0.6, TopLayer to BottomLayer, 40 vias
v3: diameter 0.6, hole 0.3, TopLayer to BottomLayer, 3 vias

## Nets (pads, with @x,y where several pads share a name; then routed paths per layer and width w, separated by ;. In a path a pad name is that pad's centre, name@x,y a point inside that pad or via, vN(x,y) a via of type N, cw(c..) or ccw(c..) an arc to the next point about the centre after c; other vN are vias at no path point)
24VGND_IN: C01.1 C2.2 C5.2 C6.2 D2.1 J4.1 J5.3 J6.1 P2_1.1 P5.2 P6.4 P11.3 P11.4 pad.@3.925,22.425 RF1.1 U2.3 U2.5 U2.6 | length 39.7
  TopLayer w0.7: v2(56.503,31.097) C2.2@56.503,32.475 ; C5.2@67.296,32.575 RF1.1@67.296,36.754
  TopLayer w1.2: v2(44.8,40.375) 44.8,42.45 v2(46.875,42.45) ; v2(56.25,54.575) C6.2@58.404,54.575 v2(58.404,52.496) ; U2.5@64.225,44 70.275,44 v2(73.675,47.4) U2.3@64.225,47.4
  TopLayer w1.5: P2_1.1@65.5,27.85 67.296,29.646 C5.2@67.296,32.575
  other v2: 67.325,35.525 70.925,43.675 73.625,43.675 76.2,43.675 66.925,43.95 76.25,45.5 70.975,45.55 73.625,45.55 66.825,47.325 70.975,47.375 76.25,47.425 70.975,49.125 73.625,49.15 76.25,49.175 76.25,50.925 70.975,50.95 73.625,50.95
232RX: R8.1 R33.2 U4.13 | length 22.1
  TopLayer w0.3: R33.2@101.628,79.15 100.9,79.15 100.425,79.625 100.425,83.45 106.475,89.5 107.7,89.5 108.5,90.3 v1(108.5,92.95) 108.5,92.975 107.95,93.525 U4.13@106.51,93.525
  BottomLayer w0.3: R8.1@107.547,93.3 108.15,93.3 v1(108.5,92.95)
232TX: R31.1 R34.2 U4.14 | length 21.5
  TopLayer w0.3: R34.2@101.628,80.975 101.628,83.603 106.55,88.525 107.95,88.525 109.45,90.025 109.45,93.2 108.475,94.175 U4.14@106.51,94.175
  BottomLayer w0.3: R31.1@107.525,91.575 v1(109.375,91.575)
+12V: D7.2 D8.2 D10.2 FB5.2 K1.5 K2.5 K3.5 P10.8 P10.9 VR3.2 | length 208.2
  TopLayer w0.8: K1.5@16.394,40.85 18.2,42.656 D7.2@18.2,44.075 ; K2.5@25.544,40.9 26.4,41.756 D8.2@26.4,44.372 ; K3.5@34.619,40.925 D10.2@34.619,44.422 ; v2(100.45,69.775) FB5.2@101.622,69.775 v2(101.622,68.397)
  TopLayer w1.5: P10.8@30.755,97.225 30.78,97.25 VR3.2@30.78,101.5
  BottomLayer w1: K1.5@16.394,40.85 16.394,39.1 16.369,39.075 17.544,37.9 26.719,37.9 ; K2.5@25.544,40.9 25.544,39.075 26.719,37.9 ; K3.5@34.619,40.925 34.619,39.4 33.119,37.9 26.719,37.9
  BottomLayer w1.5: K1.5@16.394,40.85 20.244,44.7 30.025,44.7 31.525,46.2 31.525,94.075 30.755,94.845 30.755,105.88 32.575,107.7 110.55,107.7 v2@114.8,103.45
  other v2: 112.625,103.425 114.775,103.45 112.625,105.3 114.775,105.3
+24V_IN: C6.1 J6.2 P6.3 P11.1 P11.2 R19.1 U2.1 | length 64
  TopLayer w1.2: v2(53.342,28.033) R19.1@55.585,28.033 v2(55.585,26.335) ; U2.1@64.19,50.835 C6.1@64.19,54.3 ; C6.1@64.89,54.492 v2(66.783,54.492)
  TopLayer w2: J6.2@11.764,13.05 11.764,25.936 3,34.7 3,43.7 6.525,47.225 P11.2@21.94,47.225
  other v2: 64.25,52.25
CARD_D: J7.9 J21.15 R1.1 | length 35.9
  TopLayer w0.3: J7.9@71.344,100.85 71.344,99.05 71.644,98.75 R1.1@71.644,96.2 72.494,96.2 72.919,95.775 72.919,92.506 74.575,90.85 76.745,90.85 88.925,78.67 J21.15@93.594,78.67
CURA: J4.2 P6.1 | length 10.6
  TopLayer w1.2: J4.2@88.049,13.1 89.175,14.226 P6.1@89.175,23.275
CURB: J5.2 P5.1 | length 11.6
  TopLayer w1.2: J5.2@72.799,13.1 76.125,16.426 P5.1@76.125,23.35
DE485: J20.12 R45.2 | length 42.4
  TopLayer w0.3: R45.2@52.272,61.225 52.75,61.225 v1(53.225,60.75)
  BottomLayer w0.3: J20.12@48.634,83.75 47.409,84.975 44,84.975 41.575,82.55 41.575,62.4 43.475,60.5 52.975,60.5 v1(53.225,60.75)
DE485_C: P8.4 Q6.3 R39.2 R45.1 | length 11.5
  TopLayer w0.5: Q6.3@45.275,58.2 50.45,58.2 50.878,58.628 R39.2@50.878,59.425 50.878,64.308 P8.4@50.895,64.325
DVDD: C11.1 CA3.1 FB1.2 R6.1 R9.1 R10.1 R12.1 U5.14 | length 22
  TopLayer w0.3: C11.1@96.445,38.125 100.37,38.125 101.106,37.389 U5.14@101.106,34.896
  TopLayer w0.5: R10.1@95.095,34.85 95.095,35.225 96.445,36.575 C11.1@96.445,38.125 96.445,40.023 CA3.1@96.343,40.125
  TopLayer w0.6: R9.1@95.095,29.2 R10.1@95.095,34.85
  TopLayer w0.7: CA3.1@95.495,40.552 95.922,40.125 96.343,40.125 FB1.2@98.373,40.125
EARTH: C01.2 J3.3 J4.3 J5.1 J6.3 P9.1 pad.1@15,4 pad.2@115,4 pad.@7.1,22.425 | length 154.1
  TopLayer w1.5: J6.3@6.684,13.05 7.125,13.491 C01.2@7.125,22.425
  BottomLayer w1.2: J3.3@62.675,13.171 P9.1@62.675,23.3 ; 93,6.725 93.129,6.854
  BottomLayer w1.5: J6.3@6.684,13.05 6.684,12.316 pad.1@15,4 ; pad.1@15.019,3.975 17.769,6.725 68.8,6.725 ; 62.604,6.76 J3.3@62.604,13.1 ; J5.1@67.719,13.1 67.719,7.806 68.8,6.725 ; 93.129,6.854 J4.3@93.129,13.1 ; pad.2@115.044,3.975 95.75,3.975 93,6.725 68.8,6.725
GND: C1.2 C4.1 C9.1 C15.2 C16.2 C27.1 C40.2 C61.2 C62.2 C63.2 C64.2 C65.2 CA1.2 FB4.3 J7.6 J7.10 J8.7 J8.8 J12.6 J20.2 J20.8 J20.10 J20.14 J20.20 J21.6 J21.14 J21.20 LD1.2 P1.2 P4.2 P8.2 P10.3 P10.4 P10.6 P10.7 Q3.2 Q4.2 Q5.2 Q6.2 R29.1 R48.2 R51.2 R54.2 R58.2 U3.2 U3.8 U4.15 VR2.1 VR3.1 | length 194.2
  TopLayer w0.4: C40.2@106.372,101.07 C27.1@108.225,101.07 ; U4.15@106.51,94.825 v1@109.15,94.825
  TopLayer w0.5: v1(41,58.225) 41.975,57.25 Q6.2@43.175,57.25 ; v1(45.675,59.5) R48.2@46.978,59.5 ; v1@65.644,93.45 C4.1@65.644,94.825 ; v1(69.769,92.45) 69.769,91.056 71.75,89.075 v1(73.068,89.075) 75.72,89.075 v1(88.494,76.3) ; v1@98.005,54.285 U3.8@98.005,56.5 ; v1(105.62,54.45) 105.625,54.455 U3.2@105.625,56.5 ; C1.2@110.545,57.922 C9.1@112.273,57.922 ; C9.1@112.423,57.922 C9.1@112.445,57.9
  TopLayer w0.6: Q4.2@30.744,51.4 29.022,51.4 R54.2@28.544,51.878 27.347,51.878 26.825,52.4 26.825,54.225 31.028,58.428 R51.2@32.469,58.428 32.972,57.925 Q3.2@35.044,57.925 ; R58.2@35.294,51.928 v1(35.822,51.4) Q5.2@37.719,51.4 ; R29.1@49.594,105.425 49.594,103.478 C16.2@49.597,103.475 v2(49.597,100.497) ; C65.2@54.241,88.275 55.969,88.275 v1(55.994,88.3) ; C64.2@54.241,90.45 56.145,90.45 v1(56.169,90.475) ; C63.2@54.241,92.6 56.12,92.6 v1(56.144,92.625) ; C62.2@54.241,94.875 v1(56.069,94.875) ; C61.2@54.241,97.05 56.12,97.05 v1(56.144,97.075) ; v1(57.744,100.05) 57.767,100.073 J7.10@57.767,101.612 ; v1(68.019,99.325) 68.044,99.35 J7.6@68.044,100.85 ; J7.10@72.621,101.612 72.621,100.229 v1(72.875,99.975) ; v1(100.394,71.875) C15.2@101.622,71.875 ; v1(106.3,102.375) 106.344,102.331 C40.2@106.344,101.097
  TopLayer w0.7: FB4.3@39.368,100.325 v2(39.368,102.668)
  TopLayer w0.8: v1(55.394,111.35) J7.10@56.994,111.35 ; J7.10@72.494,111.35 v1(74.294,111.35) ; v1@114.077,60.97 CA1.2@115.55,59.497 ; CA1.2@115.625,60.022 v1@115.625,61.645
  TopLayer w1: VR2.1@36.124,101.862 v2(36.124,103.426)
  TopLayer w1.5: VR3.1@27.789,101.5 27.789,97.651 P10.7@28.215,97.225
  BottomLayer w0.4: 82.625,62.075 v1(97.75,62.075) 99.375,62.075 102.4,59.05 v1(106.075,59.05)
  BottomLayer w0.5: v1(43.775,83.375) 42.425,82.025 42.425,68.425 v1(44,66.85) ; v1@58.194,75.181 65.825,67.55 78.35,67.55 J12.6@81.575,64.325 81.575,62.8 82.3,62.075 82.625,62.075 ; v1(65.744,93.35) 66.644,92.45 v1(69.769,92.45) v1(72.019,92.45)
  BottomLayer w0.6: v1@100.125,77.525 100.125,85.25 v1(102.25,87.375) ; v1@100.275,71.875 v1(100.275,77.375)
  other v1: 115.65,54 113.475,54.025 111.45,54.075 109.275,54.1 95.225,54.275 97.995,54.275 33.65,57.85 111.42,57.875 114.05,60.97 68.55,61.25 71.075,61.25 115.575,61.695 53.4,62.375 55.975,62.375 80.15,62.55 62.25,63.375 78.3,67.425 65.975,67.575 56.2,68 52.125,68.5 48.175,68.625 66.769,70 62.475,70.775 84.275,73.25 72.7,74.525 58.075,75.325 81.9,75.9 105.225,79.475 56.075,79.65 89.725,79.775 64.25,79.875 74.475,83.15 103.075,83.25 100.25,85.075 79.2,85.55 81.9,87.675 61.575,87.925 105.05,89.8 110.75,90.725 109.15,94.8 74.05,95.25
GND_ISO: C3.2 C8.2 C17.2 C24.2 C25.2 C29.1 C31.2 C33.2 C34.2 C35.2 C36.2 C37.2 CA2.2 FB3.1 pad.@118.6,25.625 pad.@123.775,29.1 R22.2 U3.9 U3.15 U5.8 U5.10 U5.12 U14.2 U15.10 U15.13 U15.15 U15.16 | length 50.6
  TopLayer w0.3: U5.12@102.406,34.896 102.406,36.661 v1(102.87,37.125) 103.37,37.125 103.706,36.789 U5.10@103.706,34.896 ; v1(112.919,38.875) 112.919,38.822 v1@112.966,38.775 ; U15.16@113.319,37.625 113.319,38.422 v1@112.966,38.775 ; U15.15@113.969,37.625 113.969,38.7 113.894,38.775 ; U15.13@115.269,37.625 115.269,38.375 114.869,38.775 113.894,38.775 ; U15.10@117.219,37.625 117.219,39.345 v1(117.475,39.6) ; v1@112.966,38.775 113.894,38.775
  TopLayer w0.4: U5.8@104.334,29.054 105.391,29.054 v1(105.42,29.025)
  TopLayer w0.5: v1@109.019,41.85 109.294,41.575 C29.1@110.119,41.575 C29.1@109.994,41.45 ; CA2.2@111.32,48.677 CA2.2@111.393,48.75 ; C8.2@114.52,44.778 v3(115.345,44.778) ; C31.2@117.044,40.853 117.044,40.031 v1(117.475,39.6)
  TopLayer w0.6: v1@99.195,26.3 C17.2@100.548,26.3 ; v1@102.35,40.772 C35.2@103.695,40.772 ; U3.15@105.625,47.229 v1@105.625,49.73 ; C25.2@109.328,31.175 109.328,30.328 v1(109.325,30.325) 110.672,28.978 R22.2@110.672,28.7 ; v1(112.97,49.525) 112.981,49.537 C3.2@114.526,49.537 115.689,50.7 117.572,50.7 U14.2@118.725,49.547 v1(122.153,49.547) 122.712,48.988 C34.2@122.712,48.299 ; v3(115.345,44.778) 115.373,44.75 C33.2@116.378,44.75 ; C37.2@118.196,25.858 C37.2@118.55,26.212 ; C36.2@122.496,29.058 pad.@123.708,29.058
  TopLayer w0.7: v1@96.891,47.229 U3.9@98.005,47.229 ; FB3.1@99.77,42.125 100.997,42.125 v1@102.35,40.772
  TopLayer w0.8: v1(109.57,47.675) 110.318,47.675 CA2.2@111.32,48.677 112.122,48.677 v1(112.97,49.525) ; C24.2@110.145,36.752 111.717,36.752 v1(111.719,36.75)
  other v1: 99.17,26.325 102.35,27.55 105.1,27.675 93.975,30.025 102.05,31.8 94,32 93.975,34 111.75,35.425 115.85,35.925 118.25,35.925 121.05,35.975 122.95,36 125.05,36.7 108.725,36.8 111.775,38.825 126.175,38.825 102.35,40.825 126.2,41.225 109.019,41.775 106.369,42.35 96.87,47.25 105.645,49.75 116.025,50.65 102.75,50.7 104.625,50.7 112.944,50.7 107.5,50.725 109.925,50.725 100.075,50.75 97.344,50.775
GUARD: J2.3 P3.4 U15.4 U15.6 | length 101.4
  TopLayer w0.3: J2.3@108.379,13.1 110.95,13.1 111.275,13.425 ; P3.4@112.505,23.3 112.505,15.455 v1(111.275,14.225) 111.275,13.425 ; 112.55,24.275 115.05,26.775 115.05,29.8 115.269,30.02 U15.4@115.269,31.225 115.269,32.325 115.494,32.55 v1(115.885,32.55) 116.275,32.55 116.569,32.256 U15.6@116.569,31.225 116.569,29.981 116.875,29.675 116.875,24.75 116.275,24.15 116.275,18.25 115.412,17.387 v1(115.412,12.213) 114.325,11.125 112.35,11.125 v1(111.275,12.2) 111.275,13.425
  TopLayer w0.5: 112.55,24.275 112.55,23.625 P3.4@112.875,23.3
  BottomLayer w0.3: v1@111.275,12.175 111.275,14.25 v1(112.5,15.475) 112.5,24.225 115.05,26.775 115.05,29.825 115.25,30.025 115.25,32.325 115.475,32.55 v1(115.885,32.55) 116.275,32.55 116.6,32.225 116.6,29.925 116.925,29.6 116.925,24.8 116.275,24.15 116.275,18.25 115.375,17.35 115.375,12.15 114.35,11.125 112.325,11.125 v1@111.275,12.175
  other v1: 115.4,14.675 115.45,17.425 112.475,19.175 116.275,19.175 116.275,21.625 112.475,21.65 116.275,24.1 112.85,24.525 114.15,25.825 116.95,28.475 115.05,28.5
KEY_IN1: C61.1 J12.1 J20.1 R59.1 | length 68.7
  TopLayer w0.3: R59.1@41.119,96.3 45.945,96.3 J20.1@46.094,96.45 46.094,97.325 46.794,98.025 51.87,98.025 C61.1@52.844,97.05 52.769,96.975 52.769,96.325 52.994,96.1 v1(55.419,96.1)
  BottomLayer w0.3: v1(55.419,96.1) 59.775,96.1 88.55,67.325 91.15,67.325 J12.1@94.15,64.325
KEY_IN2: C62.1 J12.2 J20.3 R60.1 | length 64.4
  TopLayer w0.3: R60.1@41.119,94.425 43.769,94.425 44.285,93.91 J20.3@46.094,93.91 47.31,95.125 52.595,95.125 C62.1@52.844,94.875 52.844,94.125 53.244,93.725 v1(55.444,93.725)
  BottomLayer w0.3: v1(55.444,93.725) 58.1,93.725 59.337,92.488 62.263,92.488 88.35,66.4 89.535,66.4 J12.2@91.61,64.325
KEY_IN3: C63.1 J12.3 J20.4 R61.1 | length 61.6
  TopLayer w0.3: R61.1@41.119,92.725 42.42,92.725 v1(42.469,92.775) ; J20.4@48.634,93.91 49.935,93.91 51.244,92.6 C63.1@52.844,92.6 52.844,91.8 53.144,91.5 v1@55.469,91.5
  BottomLayer w0.3: v1(42.469,92.775) 42.644,92.6 47.325,92.6 J20.4@48.634,93.91 ; v1(55.469,91.525) 62.325,91.525 89.07,64.78 J12.3@89.07,64.325
KEY_IN4: C64.1 J12.4 J20.5 R62.1 | length 59.8
  TopLayer w0.3: R62.1@41.119,90.575 43.72,90.575 44.514,91.37 J20.5@46.094,91.37 46.094,91.7 46.969,92.575 49.344,92.575 51.469,90.45 C64.1@52.844,90.45 52.844,89.625 53.119,89.35 55.419,89.35 v1(55.444,89.325)
  BottomLayer w0.3: v1(55.444,89.325) 63.55,89.325 86.53,66.345 J12.4@86.53,64.325
KEY_IN5: C65.1 J12.5 J20.6 R63.1 | length 58.4
  TopLayer w0.3: R63.1@41.119,88.4 42.969,88.4 44.694,90.125 47.39,90.125 J20.6@48.634,91.37 51.729,88.275 C65.1@52.844,88.275 52.794,88.225 52.794,86.775 v1(52.869,86.7)
  BottomLayer w0.3: v1(52.869,86.7) 52.894,86.675 65.275,86.675 83.99,67.96 J12.5@83.99,64.325
L_AIN: C16.1 J20.7 PQ1.2 R29.2 | length 46.1
  TopLayer w0.3: J20.7@46.094,88.83 47.274,87.65 49.494,87.65 51.369,85.775
  TopLayer w0.4: C16.1@50.994,103.475 51.45,103.475 58.169,96.756 58.169,88.65 55.294,85.775 51.369,85.775
  TopLayer w0.6: PQ1.2@47.994,114.785 49.665,114.785 50.966,113.484 R29.2@50.966,105.422 ; C16.1@50.974,103.495 C16.1@50.994,103.475 50.994,105.422 R29.2@50.991,105.425
LCD_BUSY: D6.1 J21.10 R32.2 | length 23.5
  TopLayer w0.3: D6.1@87.857,85.075 94.92,85.075 J21.10@96.134,86.29
  TopLayer w0.4: J21.10@96.134,86.29 97.26,86.29 98.6,84.95 98.6,77.075 101.225,74.45 ; R32.2@101.574,74.473 R32.2@101.622,74.425 R32.2@101.669,74.425
LED_S1: J21.7 R37.1 | length 21.7
  TopLayer w0.3: R37.1@87.8,105.5 87.8,96.45 91.55,92.7 94.225,92.7 94.825,92.1 94.825,90.061 J21.7@93.594,88.83
LED_S2: J21.5 R36.1 | length 21
  TopLayer w0.3: R36.1@83.375,105.525 85.1,105.525 86.1,104.525 86.1,96.2 90.93,91.37 J21.5@93.594,91.37
MCU_RXD1: J21.8 R8.2 U4.12 | length 16.2
  TopLayer w0.3: J21.8@96.134,88.83 100.974,88.83 103.075,90.931 v1(103.075,91.3) 104.65,92.875 U4.12@106.51,92.875
  BottomLayer w0.3: v1(103.075,91.3) 105.075,93.3 R8.2@106.15,93.3
MCU_TXD1: J21.9 R31.2 U4.11 | length 17.2
  TopLayer w0.3: J21.9@93.594,86.29 94.83,87.525 100.7,87.525 105.253,92.078 106.363,92.078 U4.11@106.51,92.225
  BottomLayer w0.3: v1(104.45,91.275) 104.75,91.575 R31.2@106.128,91.575
MISO1: J20.18 R28.2 R44.2 U3.6 | length 68.9
  TopLayer w0.25: v1(100.47,54.45) 100.545,54.525 U3.6@100.545,56.5
  TopLayer w0.3: v1(51.494,76.125) 52.619,75 R44.2@52.947,75 ; R28.2@100,59.778 100.545,59.234 U3.6@100.545,56.5
  BottomLayer w0.25: v1(100.47,54.45) v1@100.52,54.45
  BottomLayer w0.3: J20.18@48.634,76.13 51.495,76.13 65.15,62.475 73.775,62.475 76.875,59.375 96.525,59.375 100.47,55.431 v1(100.47,54.45)
MISO2: J7.7 J21.17 R14.1 | length 39.6
  TopLayer w0.3: J7.7@69.144,100.85 69.144,99.075 69.694,98.525 R14.1@69.694,96.2 70.3,96.2 70.669,95.831 70.669,91.506 72.2,89.975 76.37,89.975 90.215,76.13 J21.17@93.594,76.13
MOSI1: J20.17 P4.4 R27.2 R43.2 U3.5 | length 73.5
  TopLayer w0.25: v1(101.795,54.45) 101.815,54.47 U3.5@101.815,56.5
  TopLayer w0.3: v1(51.719,77.375) 52.244,76.85 R43.2@52.947,76.85 ; U3.5@101.815,56.5 R27.2@101.815,59.878
  BottomLayer w0.25: v1(101.795,54.45) v1@101.82,54.45
  BottomLayer w0.3: J20.17@46.094,76.13 47.34,77.375 v1(51.719,77.375) 53.144,77.375 64.669,65.85 72.07,65.85 P4.4@73.595,64.325 77.72,60.2 97.475,60.2 101.795,55.881 v1(101.795,54.45)
MOSI2: J7.3 J21.16 R17.1 | length 58.1
  TopLayer w0.3: J7.3@64.744,100.85 64.744,99.1 63.594,97.95 R17.1@63.594,96.225 64.294,96.225 64.669,95.85 64.669,92.731 70.525,86.875 75.144,86.875 89.944,72.075 97.194,72.075 97.844,72.725 97.844,76.96 J21.16@96.134,78.67
NetC2_1: C2.1 C5.1 CF.2 L4.2 P2_1.2 R19.2 RF2.1 | length 31.5
  TopLayer w0.7: C2.1@57.9,32.475 C5.1@61.1,32.475
  TopLayer w1: C5.1@61.1,32.475 C5.1@61.2,32.575 61.742,33.117 RF2.1@61.742,37.31 61.762,37.329 CF.2@64.533,37.329
  TopLayer w1.5: L4.2@53.775,39.025 54.75,39.025 C5.1@61.2,32.575 ; R19.2@57.871,28.033 P2_1.2@62.777,28.033 ; C5.1@61.1,32.475 61.1,29.71 P2_1.2@62.777,28.033 ; P2_1.2@62.96,27.85 P2_1.2@62.777,28.033
NetC11_2: C11.2 CA3.2 FB3.2 | length 10.5
  TopLayer w0.6: C11.2@95.048,38.125 93.645,39.528 93.645,42.252 CA3.2@95.232,43.84 ; CA3.2@95.585,43.84 97.3,42.125 FB3.2@98.373,42.125
NetC15_1: C15.1 FB5.1 J8.1 J8.2 | length 9.7
  TopLayer w0.8: FB5.1@103.019,69.775 C15.1@103.019,71.875 108.031,71.875 J8.2@108.041,71.865
  TopLayer w1: J8.1@108.041,69.325 J8.2@108.041,71.865
NetC17_1: C17.1 R3.2 U5.7 | length 4.6
  TopLayer w0.3: R3.2@103.584,26.389 R3.2@103.673,26.3 ; R3.2@103.684,26.3 U5.7@103.684,29.054
  TopLayer w0.5: C17.1@101.945,26.3 R3.2@103.673,26.3
NetC26_1: C26.1 U4.1 | length 6.6
  TopLayer w0.3: U4.1@100.769,95.475 101.569,96.275 101.569,100.6 102.094,101.125 C26.1@102.519,101.125
NetC26_2: C26.2 U4.3 | length 7.1
  TopLayer w0.3: U4.3@100.769,94.175 102.144,94.175 102.544,94.575 102.544,99.703 C26.2@102.519,99.728
NetC28_1: C28.1 U4.2 | length 7.1
  TopLayer w0.3: C28.1@100.344,99.75 100.344,97.4 98.944,96 98.944,95.175 99.294,94.825 U4.2@100.769,94.825
NetC29_2: C29.2 C30.1 R20.2 U5.5 | length 22.5
  TopLayer w0.4: U5.5@102.384,29.054 102.384,30.559 103.075,31.25 104.57,31.25 105.495,32.175 105.495,38.225
  TopLayer w0.5: 105.495,38.225 105.495,40.17 108.297,42.972 C29.2@110.119,42.972 110.122,42.975 C30.1@113.569,42.975
NetC30_2: C30.2 C31.1 R25.2 U5.6 | length 25
  TopLayer w0.3: U5.6@103.034,29.054 103.034,30.089 103.295,30.35 104.581,30.35 106.22,31.989 106.22,37.375 v1(106.72,37.875)
  TopLayer w0.35: v3(113.969,40.525) 113.569,40.925 C30.2@113.569,41.578 113.9,41.578 R25.2@115.319,42.997 116.297,42.997 C31.1@117.044,42.25 C31.1@117.041,42.247
  BottomLayer w0.35: v1(106.72,37.875) 109.345,40.5 v3@113.969,40.5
